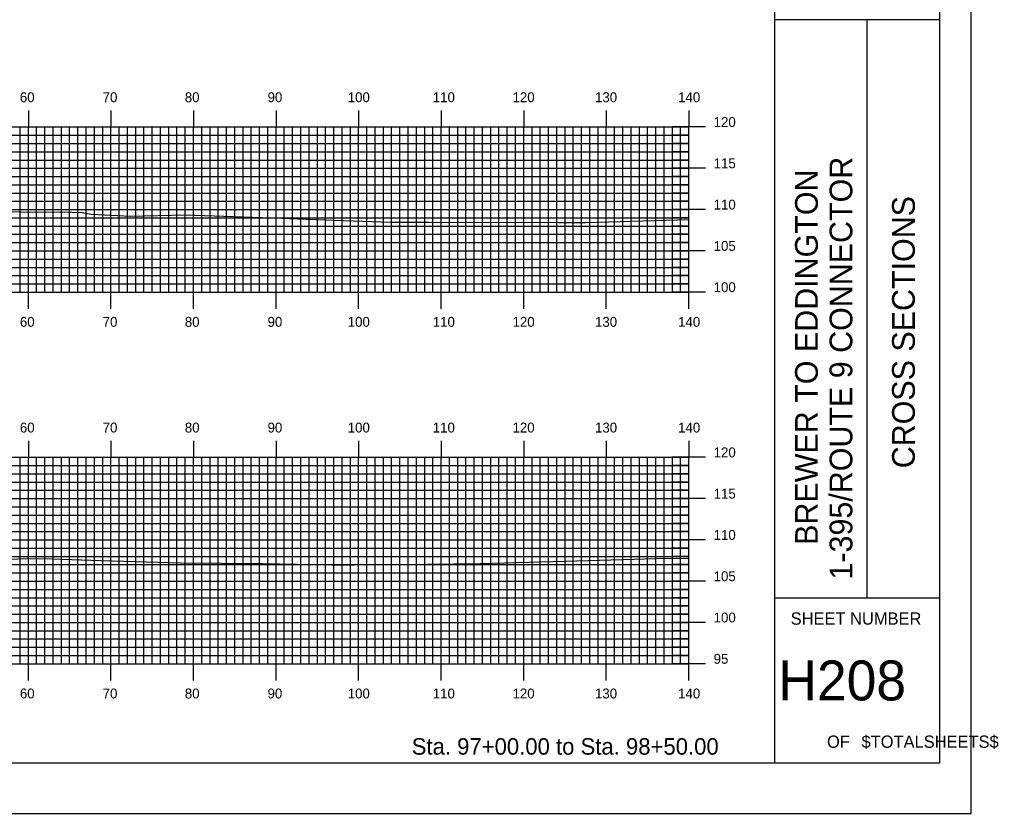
# Model space of a CAD drawing. Extents: x 1766120 to 1766463, y 442591 to 442811.
# Drawn here: x 1766344.3 to 1766462.9, y 442590.5 to 442686.7 of the extents above; entities that cross this region are included whole.
import ezdxf

# ---------------------------------------------------------------- set-up
doc = ezdxf.new("R2010")
doc.units = 0
for name, color, linetype in [('BORDER', 7, 'Continuous'), ('H_V ANNOTATION', 7, 'Continuous'), ('MAJOR', 7, 'Continuous'), ('MINOR', 7, 'Continuous'), ('PLOT BOUNDARY', 7, 'Continuous'), ('S_Roadway_Centerline', 7, 'Continuous')]:
    doc.layers.add(name, color=color, linetype=linetype)

msp = doc.modelspace()

# ---------------------------------------------------------------- linework, layer by layer
at = {"layer": 'BORDER'}
for p, q in [((1766435.8, 442596.67), (1766435.8, 442806.67)), ((1766435.8, 442686.67), (1766455.8, 442686.67)), ((1766446.98, 442616.67), (1766446.98, 442686.67)), ((1766435.8, 442616.67), (1766455.8, 442616.67))]:
    msp.add_line(p, q, dxfattribs=at)
msp.add_lwpolyline([(1766135.8, 442596.67), (1766455.8, 442596.67), (1766455.8, 442806.67), (1766135.8, 442806.67)], close=True, dxfattribs=at)
at = {"layer": 'MAJOR'}
for p, q in [((1766345.4, 442675.67), (1766345.4, 442673.67)), ((1766355.4, 442675.67), (1766355.4, 442673.67)), ((1766365.4, 442675.67), (1766365.4, 442673.67)), ((1766375.4, 442675.67), (1766375.4, 442673.67)), ((1766385.4, 442675.67), (1766385.4, 442673.67)), ((1766395.4, 442675.67), (1766395.4, 442673.67)), ((1766405.4, 442675.67), (1766405.4, 442673.67)), ((1766415.4, 442675.67), (1766415.4, 442673.67)), ((1766425.4, 442675.67), (1766425.4, 442673.67)), ((1766145.4, 442673.67), (1766425.4, 442673.67)), ((1766145.4, 442673.67), (1766425.4, 442673.67)), ((1766345.4, 442653.67), (1766345.4, 442673.67)), ((1766355.4, 442653.67), (1766355.4, 442673.67)), ((1766365.4, 442653.67), (1766365.4, 442673.67)), ((1766375.4, 442653.67), (1766375.4, 442673.67)), ((1766385.4, 442653.67), (1766385.4, 442673.67)), ((1766395.4, 442653.67), (1766395.4, 442673.67)), ((1766405.4, 442653.67), (1766405.4, 442673.67)), ((1766415.4, 442653.67), (1766415.4, 442673.67)), ((1766427.4, 442673.67), (1766423.39, 442673.67)), ((1766425.4, 442653.67), (1766425.4, 442673.67)), ((1766425.4, 442653.67), (1766425.4, 442673.67)), ((1766145.4, 442668.67), (1766425.4, 442668.67)), ((1766427.4, 442668.67), (1766423.39, 442668.67)), ((1766145.4, 442663.67), (1766425.4, 442663.67)), ((1766427.4, 442663.67), (1766423.39, 442663.67)), ((1766145.4, 442658.67), (1766425.4, 442658.67)), ((1766427.4, 442658.67), (1766423.39, 442658.67)), ((1766145.4, 442653.67), (1766425.4, 442653.67)), ((1766145.4, 442653.67), (1766425.4, 442653.67)), ((1766345.4, 442651.66), (1766345.4, 442653.67)), ((1766355.4, 442651.66), (1766355.4, 442653.67)), ((1766365.4, 442651.66), (1766365.4, 442653.67)), ((1766375.4, 442651.66), (1766375.4, 442653.67)), ((1766385.4, 442651.66), (1766385.4, 442653.67)), ((1766395.4, 442651.66), (1766395.4, 442653.67)), ((1766405.4, 442651.66), (1766405.4, 442653.67)), ((1766415.4, 442651.66), (1766415.4, 442653.67)), ((1766427.4, 442653.67), (1766423.39, 442653.67)), ((1766425.4, 442651.66), (1766425.4, 442653.67)), ((1766345.4, 442635.67), (1766345.4, 442633.67)), ((1766355.4, 442635.67), (1766355.4, 442633.67)), ((1766365.4, 442635.67), (1766365.4, 442633.67)), ((1766375.4, 442635.67), (1766375.4, 442633.67)), ((1766385.4, 442635.67), (1766385.4, 442633.67)), ((1766395.4, 442635.67), (1766395.4, 442633.67)), ((1766405.4, 442635.67), (1766405.4, 442633.67)), ((1766415.4, 442635.67), (1766415.4, 442633.67)), ((1766425.4, 442635.67), (1766425.4, 442633.67)), ((1766145.4, 442633.67), (1766425.4, 442633.67)), ((1766145.4, 442633.67), (1766425.4, 442633.67)), ((1766345.4, 442608.67), (1766345.4, 442633.67)), ((1766355.4, 442608.67), (1766355.4, 442633.67)), ((1766365.4, 442608.67), (1766365.4, 442633.67)), ((1766375.4, 442608.67), (1766375.4, 442633.67)), ((1766385.4, 442608.67), (1766385.4, 442633.67)), ((1766395.4, 442608.67), (1766395.4, 442633.67)), ((1766405.4, 442608.67), (1766405.4, 442633.67)), ((1766415.4, 442608.67), (1766415.4, 442633.67)), ((1766427.4, 442633.67), (1766423.39, 442633.67)), ((1766425.4, 442608.67), (1766425.4, 442633.67)), ((1766425.4, 442608.67), (1766425.4, 442633.67)), ((1766145.4, 442628.67), (1766425.4, 442628.67)), ((1766427.4, 442628.67), (1766423.39, 442628.67)), ((1766145.4, 442623.67), (1766425.4, 442623.67)), ((1766427.4, 442623.67), (1766423.39, 442623.67)), ((1766145.4, 442618.67), (1766425.4, 442618.67)), ((1766427.4, 442618.67), (1766423.39, 442618.67)), ((1766145.4, 442613.67), (1766425.4, 442613.67)), ((1766427.4, 442613.67), (1766423.39, 442613.67)), ((1766145.4, 442608.67), (1766425.4, 442608.67)), ((1766145.4, 442608.67), (1766425.4, 442608.67)), ((1766345.4, 442606.66), (1766345.4, 442608.67)), ((1766355.4, 442606.66), (1766355.4, 442608.67)), ((1766365.4, 442606.66), (1766365.4, 442608.67)), ((1766375.4, 442606.66), (1766375.4, 442608.67)), ((1766385.4, 442606.66), (1766385.4, 442608.67)), ((1766395.4, 442606.66), (1766395.4, 442608.67)), ((1766405.4, 442606.66), (1766405.4, 442608.67)), ((1766415.4, 442606.66), (1766415.4, 442608.67)), ((1766427.4, 442608.67), (1766423.39, 442608.67)), ((1766425.4, 442606.66), (1766425.4, 442608.67))]:
    msp.add_line(p, q, dxfattribs=at)
at = {"layer": 'MINOR'}
for p, q in [((1766344.4, 442653.67), (1766344.4, 442673.67)), ((1766346.4, 442653.67), (1766346.4, 442673.67)), ((1766347.4, 442653.67), (1766347.4, 442673.67)), ((1766348.4, 442653.67), (1766348.4, 442673.67)), ((1766349.4, 442653.67), (1766349.4, 442673.67)), ((1766350.4, 442653.67), (1766350.4, 442673.67)), ((1766351.4, 442653.67), (1766351.4, 442673.67)), ((1766352.4, 442653.67), (1766352.4, 442673.67)), ((1766353.4, 442653.67), (1766353.4, 442673.67)), ((1766354.4, 442653.67), (1766354.4, 442673.67)), ((1766356.4, 442653.67), (1766356.4, 442673.67)), ((1766357.4, 442653.67), (1766357.4, 442673.67)), ((1766358.4, 442653.67), (1766358.4, 442673.67)), ((1766359.4, 442653.67), (1766359.4, 442673.67)), ((1766360.4, 442653.67), (1766360.4, 442673.67)), ((1766361.4, 442653.67), (1766361.4, 442673.67)), ((1766362.4, 442653.67), (1766362.4, 442673.67)), ((1766363.4, 442653.67), (1766363.4, 442673.67)), ((1766364.4, 442653.67), (1766364.4, 442673.67)), ((1766366.4, 442653.67), (1766366.4, 442673.67)), ((1766367.4, 442653.67), (1766367.4, 442673.67)), ((1766368.4, 442653.67), (1766368.4, 442673.67)), ((1766369.4, 442653.67), (1766369.4, 442673.67)), ((1766370.4, 442653.67), (1766370.4, 442673.67)), ((1766371.4, 442653.67), (1766371.4, 442673.67)), ((1766372.4, 442653.67), (1766372.4, 442673.67)), ((1766373.4, 442653.67), (1766373.4, 442673.67)), ((1766374.4, 442653.67), (1766374.4, 442673.67)), ((1766376.4, 442653.67), (1766376.4, 442673.67)), ((1766377.4, 442653.67), (1766377.4, 442673.67)), ((1766378.4, 442653.67), (1766378.4, 442673.67)), ((1766379.4, 442653.67), (1766379.4, 442673.67)), ((1766380.4, 442653.67), (1766380.4, 442673.67)), ((1766381.4, 442653.67), (1766381.4, 442673.67)), ((1766382.4, 442653.67), (1766382.4, 442673.67)), ((1766383.4, 442653.67), (1766383.4, 442673.67)), ((1766384.4, 442653.67), (1766384.4, 442673.67)), ((1766386.4, 442653.67), (1766386.4, 442673.67)), ((1766387.4, 442653.67), (1766387.4, 442673.67)), ((1766388.4, 442653.67), (1766388.4, 442673.67)), ((1766389.4, 442653.67), (1766389.4, 442673.67)), ((1766390.4, 442653.67), (1766390.4, 442673.67)), ((1766391.4, 442653.67), (1766391.4, 442673.67)), ((1766392.4, 442653.67), (1766392.4, 442673.67)), ((1766393.4, 442653.67), (1766393.4, 442673.67)), ((1766394.4, 442653.67), (1766394.4, 442673.67)), ((1766396.4, 442653.67), (1766396.4, 442673.67)), ((1766397.4, 442653.67), (1766397.4, 442673.67)), ((1766398.4, 442653.67), (1766398.4, 442673.67)), ((1766399.4, 442653.67), (1766399.4, 442673.67)), ((1766400.4, 442653.67), (1766400.4, 442673.67)), ((1766401.4, 442653.67), (1766401.4, 442673.67)), ((1766402.4, 442653.67), (1766402.4, 442673.67)), ((1766403.4, 442653.67), (1766403.4, 442673.67)), ((1766404.4, 442653.67), (1766404.4, 442673.67)), ((1766406.4, 442653.67), (1766406.4, 442673.67)), ((1766407.4, 442653.67), (1766407.4, 442673.67)), ((1766408.4, 442653.67), (1766408.4, 442673.67)), ((1766409.4, 442653.67), (1766409.4, 442673.67)), ((1766410.4, 442653.67), (1766410.4, 442673.67)), ((1766411.4, 442653.67), (1766411.4, 442673.67)), ((1766412.4, 442653.67), (1766412.4, 442673.67)), ((1766413.4, 442653.67), (1766413.4, 442673.67)), ((1766414.4, 442653.67), (1766414.4, 442673.67)), ((1766416.4, 442653.67), (1766416.4, 442673.67)), ((1766417.4, 442653.67), (1766417.4, 442673.67)), ((1766418.4, 442653.67), (1766418.4, 442673.67)), ((1766419.4, 442653.67), (1766419.4, 442673.67)), ((1766420.4, 442653.67), (1766420.4, 442673.67)), ((1766421.4, 442653.67), (1766421.4, 442673.67)), ((1766422.4, 442653.67), (1766422.4, 442673.67)), ((1766423.4, 442653.67), (1766423.4, 442673.67)), ((1766424.4, 442653.67), (1766424.4, 442673.67)), ((1766145.4, 442672.67), (1766425.4, 442672.67)), ((1766425.4, 442672.67), (1766423.39, 442672.67)), ((1766145.4, 442671.67), (1766425.4, 442671.67)), ((1766425.4, 442671.67), (1766423.39, 442671.67)), ((1766145.4, 442670.67), (1766425.4, 442670.67)), ((1766145.4, 442669.67), (1766425.4, 442669.67)), ((1766425.4, 442670.67), (1766423.39, 442670.67)), ((1766425.4, 442669.67), (1766423.39, 442669.67)), ((1766145.4, 442667.67), (1766425.4, 442667.67)), ((1766425.4, 442667.67), (1766423.39, 442667.67)), ((1766145.4, 442666.67), (1766425.4, 442666.67)), ((1766425.4, 442666.67), (1766423.39, 442666.67)), ((1766145.4, 442665.67), (1766425.4, 442665.67)), ((1766425.4, 442665.67), (1766423.39, 442665.67)), ((1766145.4, 442664.67), (1766425.4, 442664.67)), ((1766425.4, 442664.67), (1766423.39, 442664.67)), ((1766145.4, 442662.67), (1766425.4, 442662.67)), ((1766425.4, 442662.67), (1766423.39, 442662.67)), ((1766145.4, 442661.67), (1766425.4, 442661.67)), ((1766425.4, 442661.67), (1766423.39, 442661.67)), ((1766145.4, 442660.67), (1766425.4, 442660.67)), ((1766425.4, 442660.67), (1766423.39, 442660.67)), ((1766145.4, 442659.67), (1766425.4, 442659.67)), ((1766425.4, 442659.67), (1766423.39, 442659.67)), ((1766145.4, 442657.67), (1766425.4, 442657.67)), ((1766145.4, 442656.67), (1766425.4, 442656.67)), ((1766425.4, 442657.67), (1766423.39, 442657.67)), ((1766425.4, 442656.67), (1766423.39, 442656.67)), ((1766145.4, 442655.67), (1766425.4, 442655.67)), ((1766425.4, 442655.67), (1766423.39, 442655.67)), ((1766145.4, 442654.67), (1766425.4, 442654.67)), ((1766425.4, 442654.67), (1766423.39, 442654.67)), ((1766344.4, 442608.67), (1766344.4, 442633.67)), ((1766346.4, 442608.67), (1766346.4, 442633.67)), ((1766347.4, 442608.67), (1766347.4, 442633.67)), ((1766348.4, 442608.67), (1766348.4, 442633.67)), ((1766349.4, 442608.67), (1766349.4, 442633.67)), ((1766350.4, 442608.67), (1766350.4, 442633.67)), ((1766351.4, 442608.67), (1766351.4, 442633.67)), ((1766352.4, 442608.67), (1766352.4, 442633.67)), ((1766353.4, 442608.67), (1766353.4, 442633.67)), ((1766354.4, 442608.67), (1766354.4, 442633.67)), ((1766356.4, 442608.67), (1766356.4, 442633.67)), ((1766357.4, 442608.67), (1766357.4, 442633.67)), ((1766358.4, 442608.67), (1766358.4, 442633.67)), ((1766359.4, 442608.67), (1766359.4, 442633.67)), ((1766360.4, 442608.67), (1766360.4, 442633.67)), ((1766361.4, 442608.67), (1766361.4, 442633.67)), ((1766362.4, 442608.67), (1766362.4, 442633.67)), ((1766363.4, 442608.67), (1766363.4, 442633.67)), ((1766364.4, 442608.67), (1766364.4, 442633.67)), ((1766366.4, 442608.67), (1766366.4, 442633.67)), ((1766367.4, 442608.67), (1766367.4, 442633.67)), ((1766368.4, 442608.67), (1766368.4, 442633.67)), ((1766369.4, 442608.67), (1766369.4, 442633.67)), ((1766370.4, 442608.67), (1766370.4, 442633.67)), ((1766371.4, 442608.67), (1766371.4, 442633.67)), ((1766372.4, 442608.67), (1766372.4, 442633.67)), ((1766373.4, 442608.67), (1766373.4, 442633.67)), ((1766374.4, 442608.67), (1766374.4, 442633.67)), ((1766376.4, 442608.67), (1766376.4, 442633.67)), ((1766377.4, 442608.67), (1766377.4, 442633.67)), ((1766378.4, 442608.67), (1766378.4, 442633.67)), ((1766379.4, 442608.67), (1766379.4, 442633.67)), ((1766380.4, 442608.67), (1766380.4, 442633.67)), ((1766381.4, 442608.67), (1766381.4, 442633.67)), ((1766382.4, 442608.67), (1766382.4, 442633.67)), ((1766383.4, 442608.67), (1766383.4, 442633.67)), ((1766384.4, 442608.67), (1766384.4, 442633.67)), ((1766386.4, 442608.67), (1766386.4, 442633.67)), ((1766387.4, 442608.67), (1766387.4, 442633.67)), ((1766388.4, 442608.67), (1766388.4, 442633.67)), ((1766389.4, 442608.67), (1766389.4, 442633.67)), ((1766390.4, 442608.67), (1766390.4, 442633.67)), ((1766391.4, 442608.67), (1766391.4, 442633.67)), ((1766392.4, 442608.67), (1766392.4, 442633.67)), ((1766393.4, 442608.67), (1766393.4, 442633.67)), ((1766394.4, 442608.67), (1766394.4, 442633.67)), ((1766396.4, 442608.67), (1766396.4, 442633.67)), ((1766397.4, 442608.67), (1766397.4, 442633.67)), ((1766398.4, 442608.67), (1766398.4, 442633.67)), ((1766399.4, 442608.67), (1766399.4, 442633.67)), ((1766400.4, 442608.67), (1766400.4, 442633.67)), ((1766401.4, 442608.67), (1766401.4, 442633.67)), ((1766402.4, 442608.67), (1766402.4, 442633.67)), ((1766403.4, 442608.67), (1766403.4, 442633.67)), ((1766404.4, 442608.67), (1766404.4, 442633.67)), ((1766406.4, 442608.67), (1766406.4, 442633.67)), ((1766407.4, 442608.67), (1766407.4, 442633.67)), ((1766408.4, 442608.67), (1766408.4, 442633.67)), ((1766409.4, 442608.67), (1766409.4, 442633.67)), ((1766410.4, 442608.67), (1766410.4, 442633.67)), ((1766411.4, 442608.67), (1766411.4, 442633.67)), ((1766412.4, 442608.67), (1766412.4, 442633.67)), ((1766413.4, 442608.67), (1766413.4, 442633.67)), ((1766414.4, 442608.67), (1766414.4, 442633.67)), ((1766416.4, 442608.67), (1766416.4, 442633.67)), ((1766417.4, 442608.67), (1766417.4, 442633.67)), ((1766418.4, 442608.67), (1766418.4, 442633.67)), ((1766419.4, 442608.67), (1766419.4, 442633.67)), ((1766420.4, 442608.67), (1766420.4, 442633.67)), ((1766421.4, 442608.67), (1766421.4, 442633.67)), ((1766422.4, 442608.67), (1766422.4, 442633.67)), ((1766423.4, 442608.67), (1766423.4, 442633.67)), ((1766424.4, 442608.67), (1766424.4, 442633.67)), ((1766145.4, 442632.67), (1766425.4, 442632.67)), ((1766425.4, 442632.67), (1766423.39, 442632.67)), ((1766145.4, 442631.67), (1766425.4, 442631.67)), ((1766145.4, 442630.67), (1766425.4, 442630.67)), ((1766425.4, 442631.67), (1766423.39, 442631.67)), ((1766425.4, 442630.67), (1766423.39, 442630.67)), ((1766145.4, 442629.67), (1766425.4, 442629.67)), ((1766425.4, 442629.67), (1766423.39, 442629.67)), ((1766145.4, 442627.67), (1766425.4, 442627.67)), ((1766425.4, 442627.67), (1766423.39, 442627.67)), ((1766145.4, 442626.67), (1766425.4, 442626.67)), ((1766425.4, 442626.67), (1766423.39, 442626.67)), ((1766145.4, 442625.67), (1766425.4, 442625.67)), ((1766145.4, 442624.67), (1766425.4, 442624.67)), ((1766425.4, 442625.67), (1766423.39, 442625.67)), ((1766425.4, 442624.67), (1766423.39, 442624.67)), ((1766145.4, 442622.67), (1766425.4, 442622.67)), ((1766425.4, 442622.67), (1766423.39, 442622.67)), ((1766145.4, 442621.67), (1766425.4, 442621.67)), ((1766425.4, 442621.67), (1766423.39, 442621.67)), ((1766145.4, 442620.67), (1766425.4, 442620.67)), ((1766425.4, 442620.67), (1766423.39, 442620.67)), ((1766145.4, 442619.67), (1766425.4, 442619.67)), ((1766425.4, 442619.67), (1766423.39, 442619.67)), ((1766145.4, 442617.67), (1766425.4, 442617.67)), ((1766425.4, 442617.67), (1766423.39, 442617.67)), ((1766145.4, 442616.67), (1766425.4, 442616.67)), ((1766425.4, 442616.67), (1766423.39, 442616.67)), ((1766145.4, 442615.67), (1766425.4, 442615.67)), ((1766425.4, 442615.67), (1766423.39, 442615.67)), ((1766145.4, 442614.67), (1766425.4, 442614.67)), ((1766425.4, 442614.67), (1766423.39, 442614.67)), ((1766145.4, 442612.67), (1766425.4, 442612.67)), ((1766145.4, 442611.67), (1766425.4, 442611.67)), ((1766425.4, 442612.67), (1766423.39, 442612.67)), ((1766425.4, 442611.67), (1766423.39, 442611.67)), ((1766145.4, 442610.67), (1766425.4, 442610.67)), ((1766425.4, 442610.67), (1766423.39, 442610.67)), ((1766145.4, 442609.67), (1766425.4, 442609.67)), ((1766425.4, 442609.67), (1766423.39, 442609.67))]:
    msp.add_line(p, q, dxfattribs=at)
at = {"layer": 'PLOT BOUNDARY'}
msp.add_lwpolyline([(1766119.61, 442590.55), (1766459.61, 442590.55), (1766459.61, 442810.55), (1766119.61, 442810.55)], close=True, dxfattribs=at)
at = {"layer": 'S_Roadway_Centerline'}
for points in [[(1766342.23, 442663.48), (1766345.34, 442663.37), (1766349.42, 442663.4), (1766351.91, 442663.33), (1766352.99, 442663.1), (1766357.81, 442662.88), (1766364.39, 442663.03), (1766376.04, 442662.62), (1766376.97, 442662.59), (1766379.04, 442662.52), (1766389.27, 442662.15), (1766393.86, 442662.13), (1766409.65, 442662.12), (1766412.2, 442662.1), (1766412.91, 442662.11), (1766414.28, 442662.16), (1766425.4, 442662.48)], [(1766335.9, 442621.11), (1766345.3, 442621.41), (1766348.31, 442621.38), (1766354.17, 442621.17), (1766363.85, 442620.89), (1766373.72, 442620.8), (1766382.1, 442620.65), (1766384.88, 442620.64), (1766390.41, 442620.69), (1766400.14, 442620.8), (1766410.42, 442621.11), (1766418.75, 442621.32), (1766421.35, 442621.4), (1766425.4, 442621.46)]]:
    msp.add_lwpolyline(points, dxfattribs=at)

# ---------------------------------------------------------------- texts
at = {"layer": 'BORDER'}
for s, p in [('1-395/ROUTE 9 CONNECTOR', (1766445.2, 442618.87)), ('BREWER TO EDDINGTON', (1766441.02, 442623.07)), ('CROSS SECTIONS', (1766452.77, 442632.34))]:
    msp.add_text(s, height=2.7557, rotation=90, dxfattribs=at).set_placement(p)
for s, height, p in [('SHEET NUMBER', 1.4905, (1766437.73, 442613.4)), ('H208', 4.839, (1766436.24, 442604.23)), ('OF', 1.491, (1766442.13, 442598.49)), ('$TOTALSHEETS$', 1.4905, (1766446.31, 442598.49))]:
    msp.add_text(s, height=height, dxfattribs=at).set_placement(p)
at = {"layer": 'H_V ANNOTATION'}
for s, height, p in [('60', 1.2, (1766344.37, 442676.67)), ('70', 1.2, (1766354.4, 442676.67)), ('80', 1.2, (1766364.35, 442676.67)), ('90', 1.2, (1766374.37, 442676.67)), ('100', 1.2, (1766384.08, 442676.67)), ('110', 1.2, (1766394.38, 442676.67)), ('120', 1.2, (1766404.04, 442676.67)), ('130', 1.2, (1766414.03, 442676.67)), ('140', 1.2, (1766424.1, 442676.67)), ('120', 1.2, (1766428.4, 442673.67)), ('115', 1.2, (1766428.4, 442668.67)), ('110', 1.2, (1766428.4, 442663.67)), ('105', 1.2, (1766428.4, 442658.67)), ('100', 1.2, (1766428.4, 442653.67)), ('60', 1.2, (1766344.37, 442649.47)), ('70', 1.2, (1766354.4, 442649.47)), ('80', 1.2, (1766364.35, 442649.47)), ('90', 1.2, (1766374.37, 442649.47)), ('100', 1.2, (1766384.08, 442649.47)), ('110', 1.2, (1766394.38, 442649.47)), ('120', 1.2, (1766404.04, 442649.47)), ('130', 1.2, (1766414.03, 442649.47)), ('140', 1.2, (1766424.1, 442649.47)), ('60', 1.2, (1766344.37, 442636.67)), ('70', 1.2, (1766354.4, 442636.67)), ('80', 1.2, (1766364.35, 442636.67)), ('90', 1.2, (1766374.37, 442636.67)), ('100', 1.2, (1766384.08, 442636.67)), ('110', 1.2, (1766394.38, 442636.67)), ('120', 1.2, (1766404.04, 442636.67)), ('130', 1.2, (1766414.03, 442636.67)), ('140', 1.2, (1766424.1, 442636.67)), ('120', 1.2, (1766428.4, 442633.67)), ('115', 1.2, (1766428.4, 442628.67)), ('110', 1.2, (1766428.4, 442623.67)), ('105', 1.2, (1766428.4, 442618.67)), ('100', 1.2, (1766428.4, 442613.67)), ('95', 1.2, (1766428.4, 442608.67)), ('60', 1.2, (1766344.37, 442604.47)), ('70', 1.2, (1766354.4, 442604.47)), ('80', 1.2, (1766364.35, 442604.47)), ('90', 1.2, (1766374.37, 442604.47)), ('100', 1.2, (1766384.08, 442604.47)), ('110', 1.2, (1766394.38, 442604.47)), ('120', 1.2, (1766404.04, 442604.47)), ('130', 1.2, (1766414.03, 442604.47)), ('140', 1.2, (1766424.1, 442604.47)), ('Sta. 97+00.00 to Sta. 98+50.00', 2.0004, (1766391.83, 442597.66))]:
    msp.add_text(s, height=height, dxfattribs=at).set_placement(p)

doc.saveas('drawing.dxf')
